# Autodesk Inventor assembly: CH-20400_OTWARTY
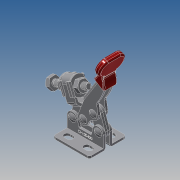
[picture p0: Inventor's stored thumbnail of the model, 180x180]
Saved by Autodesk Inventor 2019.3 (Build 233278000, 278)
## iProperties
Company: Î¢ÈíÖÐ¹ú
Created: 2012-09
Part Number: CH-20400_OTWARTY
Material: Ogólny
Description: STEP AP203
Document SubType Name: Assembly
Designer: CADENGINEERING4
Sending System: SolidWorks 2010
Preprocessor: SwSTEP 2.0
Title: CH-20400.STEP
Author: Î¢ÈíÓÃ»§
Revision Number: ÈÎºÎ
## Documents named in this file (9)
- E:\STRONA\Horizontal toggle clamp\CH-20400\CH-20400_OTWARTY.iam
- E:\STRONA\Horizontal toggle clamp\CH-20400\CH-20400-05.ipt
- E:\STRONA\Horizontal toggle clamp\CH-20400\CH-FW-080.ipt
- E:\STRONA\Horizontal toggle clamp\CH-20400\CH-20400-02 U-BAR.ipt
- E:\STRONA\Horizontal toggle clamp\CH-20400\CH-20400-03 HANDLE.ipt
- E:\STRONA\Horizontal toggle clamp\CH-20400\CH-20400-04 CONNECTING-PLATE.ipt
- E:\STRONA\Horizontal toggle clamp\CH-20400\M4 Nut.ipt
- E:\STRONA\Horizontal toggle clamp\CH-20400\CH-SA-042507 SPINDLE SUPPLIED.ipt
- E:\STRONA\Horizontal toggle clamp\CH-20400\CH-20400-01 FLANGED BASE.ipt
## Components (14 placed, 14 different names)
1. CH-20400-05_1 — Zestawiające:15, Zestawiające:16
2. CH-20400-05_2 — Zestawiające:23, Zestawiające:24
3. CH-FW-080_3 — Równoległe:2, Zestawiające:6, Zestawiające:7, Zestawiające:8
4. CH-20400-02 U-BAR_4 — Równoległe:1, Zestawiające:4, Zestawiające:8, Zestawiające:9, Zestawiające:21, Zestawiające:22, Zestawiające:25
5. CH-20400-03 HANDLE_5 — Zestawiające:17, Zestawiające:18, Zestawiające:19, Zestawiające:20, Zestawiające:25, Zestawiające:26, Zestawiające:27, Kątowe:1
6. CH-20400-04 CONNECTING-PLATE_6 — Zestawiające:10, Zestawiające:11, Zestawiające:12, Zestawiające:17
7. CH-20400-05_7 — Zestawiające:19, Zestawiające:20
8. M4 Nut_8 — Zestawiające:1, Zestawiające:3
9. CH-SA-042507 SPINDLE SUPPLIED_9 — Równoległe:3, Zestawiające:1, Zestawiające:2, Zestawiające:5, Zestawiające:6, Zestawiające:9
10. CH-FW-080_10 — Równoległe:1, Równoległe:2, Zestawiające:2, Zestawiające:3, Zestawiające:4
11. CH-20400-01 FLANGED BASE_11 — Zestawiające:13, Zestawiające:14, Zestawiające:15, Zestawiające:16, Zestawiające:21, Zestawiające:22, Zestawiające:23, Zestawiające:24, Kątowe:1
12. CH-20400-05_12 — Zestawiające:26, Zestawiające:27
13. CH-20400-04 CONNECTING-PLATE_13 — Zestawiające:10, Zestawiające:11, Zestawiające:12, Zestawiające:13, Zestawiające:14, Zestawiające:18
14. M4 Nut_14 — Równoległe:3, Zestawiające:5, Zestawiające:7
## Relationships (31: Mate 27, Flush 3, Angle 1)
- Równoległe:1 [Flush]: CH-20400-02 U-BAR_4 ↔ CH-FW-080_10
- Równoległe:2 [Flush]: CH-FW-080_3 ↔ CH-FW-080_10
- Równoległe:3 [Flush]: CH-SA-042507 SPINDLE SUPPLIED_9 ↔ M4 Nut_14
- Zestawiające:1 [Mate]: M4 Nut_8 ↔ CH-SA-042507 SPINDLE SUPPLIED_9
- Zestawiające:2 [Mate]: CH-SA-042507 SPINDLE SUPPLIED_9 ↔ CH-FW-080_10
- Zestawiające:3 [Mate]: M4 Nut_8 ↔ CH-FW-080_10
- Zestawiające:4 [Mate]: CH-20400-02 U-BAR_4 ↔ CH-FW-080_10
- Zestawiające:5 [Mate]: CH-SA-042507 SPINDLE SUPPLIED_9 ↔ M4 Nut_14
- Zestawiające:6 [Mate]: CH-FW-080_3 ↔ CH-SA-042507 SPINDLE SUPPLIED_9
- Zestawiające:7 [Mate]: CH-FW-080_3 ↔ M4 Nut_14
- Zestawiające:8 [Mate]: CH-FW-080_3 ↔ CH-20400-02 U-BAR_4
- Zestawiające:9 [Mate]: CH-20400-02 U-BAR_4 ↔ CH-SA-042507 SPINDLE SUPPLIED_9
- Zestawiające:10 [Mate]: CH-20400-04 CONNECTING-PLATE_6 ↔ CH-20400-04 CONNECTING-PLATE_13
- Zestawiające:11 [Mate]: CH-20400-04 CONNECTING-PLATE_6 ↔ CH-20400-04 CONNECTING-PLATE_13
- Zestawiające:12 [Mate]: CH-20400-04 CONNECTING-PLATE_6 ↔ CH-20400-04 CONNECTING-PLATE_13
- Zestawiające:13 [Mate]: CH-20400-01 FLANGED BASE_11 ↔ CH-20400-04 CONNECTING-PLATE_13
- Zestawiające:14 [Mate]: CH-20400-01 FLANGED BASE_11 ↔ CH-20400-04 CONNECTING-PLATE_13
- Zestawiające:15 [Mate]: CH-20400-05_1 ↔ CH-20400-01 FLANGED BASE_11
- Zestawiające:16 [Mate]: CH-20400-05_1 ↔ CH-20400-01 FLANGED BASE_11
- Zestawiające:17 [Mate]: CH-20400-03 HANDLE_5 ↔ CH-20400-04 CONNECTING-PLATE_6
- Zestawiające:18 [Mate]: CH-20400-03 HANDLE_5 ↔ CH-20400-04 CONNECTING-PLATE_13
- Zestawiające:19 [Mate]: CH-20400-03 HANDLE_5 ↔ CH-20400-05_7
- Zestawiające:20 [Mate]: CH-20400-03 HANDLE_5 ↔ CH-20400-05_7
- Zestawiające:21 [Mate]: CH-20400-02 U-BAR_4 ↔ CH-20400-01 FLANGED BASE_11
- Zestawiające:22 [Mate]: CH-20400-02 U-BAR_4 ↔ CH-20400-01 FLANGED BASE_11
- Zestawiające:23 [Mate]: CH-20400-05_2 ↔ CH-20400-01 FLANGED BASE_11
- Zestawiające:24 [Mate]: CH-20400-05_2 ↔ CH-20400-01 FLANGED BASE_11
- Zestawiające:25 [Mate]: CH-20400-02 U-BAR_4 ↔ CH-20400-03 HANDLE_5
- Zestawiające:26 [Mate]: CH-20400-03 HANDLE_5 ↔ CH-20400-05_12
- Zestawiające:27 [Mate]: CH-20400-03 HANDLE_5 ↔ CH-20400-05_12
- Kątowe:1 [Angle]: CH-20400-03 HANDLE_5 ↔ CH-20400-01 FLANGED BASE_11
